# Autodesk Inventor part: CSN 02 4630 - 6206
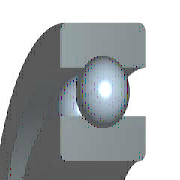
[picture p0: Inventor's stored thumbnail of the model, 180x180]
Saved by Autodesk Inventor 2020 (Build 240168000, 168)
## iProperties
IsCustomPart: 0
Created: 2019-01
Part Number: CSN 02 4630 - 6206
Material: Ocel, měkká
Description: Kuličková ložiska jednořadá
Document SubType Name: Modeling
Standard: CSN 02 4630
Designer: doma
Standards Organization: CSN
Language: cs-CZ
Size Designation: 6206
Categories: <MemberInstance><Categories><Category DisplayName="Součásti hřídele" InternalName="7f7aeb1f-a693-4053-b835-cee3144e0d98" Mnemonic="SHFT"><Category DisplayName="
Density: 7.85 g/cm^3
Appearance: Pololeštěná
Mass: 196.318 g
Surface Area: 142.005 cm^2
Volume: 25.0086 cm^3
Author: doma
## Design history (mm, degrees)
sketch "Náčrt" dims "d0" = 8.32 (= -0.26 x WD + 0.26 x BD)
  geometry: L1 (3.84, 23)-(12.16, 23); L2 (8, 23)-(8, 18.84); L3 (8, 23)-(8, 27.16); L4 (4.909, 20.216)-(0, 20.216); L5 (0, 15)-(16, 15); L6 (4.909, 25.784)-(0, 25.784); L7 (0, 31)-(16, 31); L8 (16, 15)-(16, 20.216); L9 (11.091, 20.216)-(16, 20.216); L10 (11.091, 25.784)-(16, 25.784); L11 (16, 31)-(16, 25.784); L12 (-1.4, 0)-(8.4, 0) reference; L13 (0, -0.3)-(0, 5.3) reference
  constraints: 22 end point, 4 point on line, 2 collinear, 2 perpendicular, 2 symmetric about line, 1 midpoint, 1 parallel, 14 other
  dimensions: "d9" = 30 diameter of L5 L12 (= WD); "d11" = 62 diameter of L7 L12 (= BD); "d12" = 16 distance between parallel lines of L8 L13 (= KB); "d13" = 40.432 diameter of L9 L12 (= 0.326 x BD + 0.674 x WD)
revolve "Těleso" stored, may be unused: angle "d6" = 90 deg
revolve "Kulička" stored, may be unused: angle "d7" = 90 deg
pattern_circular "Kuličky" dims angle "d3" = 360 deg
body "Solid1"
fillet "Zaoblení1" dims "d1" = 1 (= KRS)
other parameters: "WD" = 30 [user parameter; used in 5 equation terms], "BD" = 62 [user parameter; used in 5 equation terms], "KB" = 16 [user parameter; used in 1 equation term], "KRS" = 1 [user parameter; used in 1 equation term], "d4" = 0, "d5" = 0, "d8" = 0, "d14" = 0, "d15" = 0, "BBA" = 0 [user parameter], "BC0" = 1.12e+07 [user parameter], "BC" = 1.95e+07 [user parameter], "BR" = 31 (= 0.5 x BD) [user parameter], "WR" = 15 (= 0.5 x WD) [user parameter]
